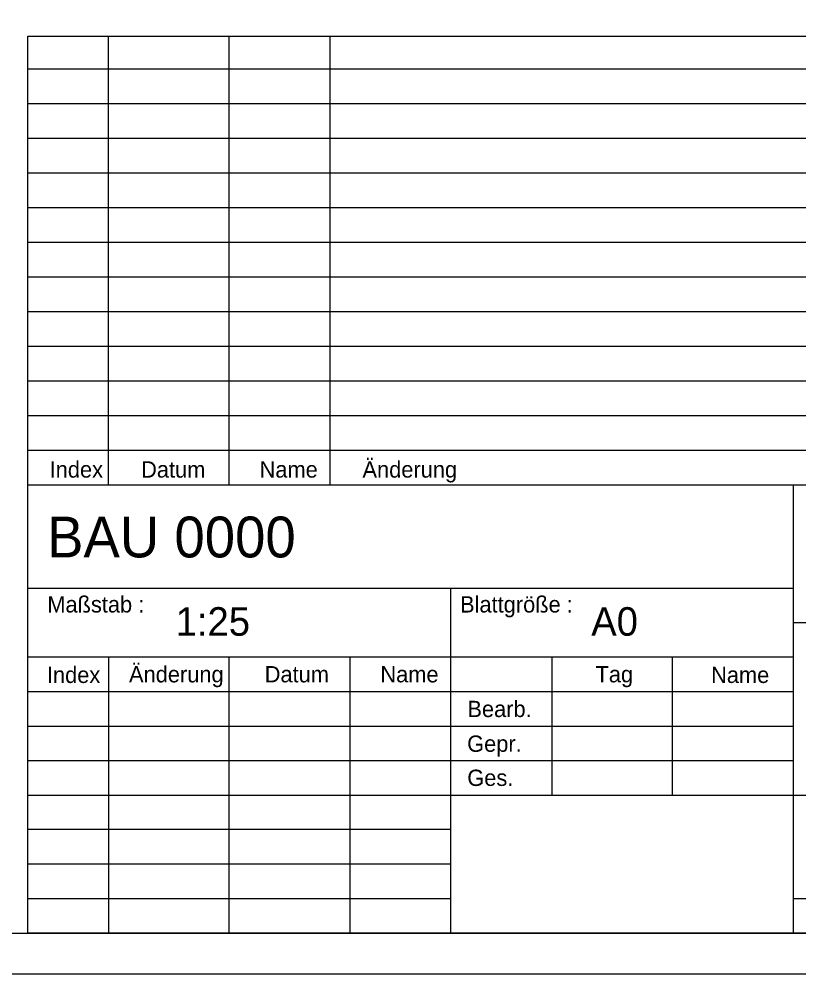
# Model space of a CAD drawing. Extents: x 0 to 29.7, y 0 to 21.
# Drawn here: x 25.127 to 27.516, y 0 to 2.927 of the extents above; entities that cross this region are included whole.
import ezdxf

# ---------------------------------------------------------------- set-up
doc = ezdxf.new("R2010")
doc.units = 0
doc.layers.add('90_Plankopf', color=7, linetype='Continuous')

msp = doc.modelspace()

# ---------------------------------------------------------------- linework, layer by layer
at = {"layer": '90_Plankopf'}
for p, q in [((25.153, 1.4998), (25.153, 2.8745)), ((25.153, 2.8745), (29.6, 2.8745)), ((25.4001, 1.4998), (25.4001, 2.8745)), ((25.7707, 1.4998), (25.7707, 2.8745)), ((26.0795, 1.4998), (26.0795, 2.8745)), ((25.153, 2.7748), (29.6, 2.7748)), ((25.153, 2.6685), (29.6, 2.6685)), ((25.153, 2.5623), (29.6, 2.5623)), ((25.153, 2.456), (29.6, 2.456)), ((25.153, 2.3498), (29.6, 2.3498)), ((25.153, 2.2435), (29.6, 2.2435)), ((25.153, 2.1373), (29.6, 2.1373)), ((25.153, 2.031), (29.6, 2.031)), ((25.153, 1.9248), (29.6, 1.9248)), ((25.153, 1.8185), (29.6, 1.8185)), ((25.153, 1.7123), (29.6, 1.7123)), ((25.153, 1.606), (29.6, 1.606)), ((25.153, 1.4998), (29.6, 1.4998)), ((25.153, 0.125), (25.153, 1.4998)), ((25.153, 1.4998), (29.6, 1.4998)), ((27.5, 0.125), (27.5, 1.4998)), ((25.153, 1.1825), (27.5, 1.1825)), ((26.4501, 0.125), (26.4501, 1.1825)), ((27.5, 1.0768), (29.6, 1.0768)), ((25.153, 0.9718), (27.5, 0.9718)), ((25.4001, 0.971), (25.4001, 0.125)), ((25.7707, 0.125), (25.7707, 0.971)), ((26.1412, 0.125), (26.1412, 0.971)), ((26.7589, 0.971), (26.7589, 0.548)), ((27.1295, 0.548), (27.1295, 0.971)), ((25.153, 0.8658), (27.5, 0.8658)), ((25.153, 0.7595), (27.5, 0.7595)), ((25.153, 0.6538), (27.5, 0.6538)), ((25.153, 0.548), (27.5, 0.548)), ((25.153, 0.548), (27.5, 0.548)), ((26.4501, 0.548), (27.5, 0.548)), ((27.5, 0.548), (29.6, 0.548)), ((26.4501, 0.4423), (25.153, 0.4423)), ((26.4501, 0.3365), (25.153, 0.3365)), ((25.153, 0.2308), (26.4501, 0.2308)), ((27.5, 0.2308), (29.6, 0.2308)), ((29.6, 0.125), (25.153, 0.125)), ((25.153, 0.125), (26.4501, 0.125)), ((25.445, 0.125), (29.6, 0.125)), ((25.445, 0.125), (29.6, 0.125))]:
    msp.add_line(p, q, dxfattribs=at)
for points in [[(0, 0), (29.725, 0), (29.725, 21.025), (0, 21.025)], [(0.625, 0.125), (29.6, 0.125), (29.6, 20.9), (0.625, 20.9)]]:
    msp.add_lwpolyline(points, close=True, dxfattribs=at)

# ---------------------------------------------------------------- texts
for s, height, p in [('Änderung', 0.05, (26.1789, 1.5214)), ('Index', 0.05, (25.2201, 1.5214)), ('Datum', 0.05, (25.5004, 1.5214)), ('Name', 0.05, (25.8635, 1.5214)), ('BAU 0000      ', 0.125, (25.2123, 1.2769)), ('Maßstab :', 0.05, (25.2129, 1.1079)), ('Blattgröße :', 0.049998, (26.4779, 1.1079)), ('1:25     ', 0.0875, (25.6065, 1.0367)), ('A0       ', 0.0875, (26.88, 1.0367)), ('Index', 0.05, (25.2117, 0.8918)), ('Änderung', 0.05, (25.4634, 0.8937)), ('Datum', 0.05, (25.8792, 0.8937)), ('Name', 0.05, (26.2337, 0.8937)), ('Tag', 0.05, (26.8931, 0.8937)), ('Name', 0.05, (27.2473, 0.8918)), ('Bearb.', 0.05, (26.5004, 0.7873)), ('Gepr.', 0.05, (26.4997, 0.6808)), ('Ges.', 0.05, (26.5001, 0.5762))]:
    msp.add_text(s, height=height, dxfattribs=at).set_placement(p)

doc.saveas('drawing.dxf')
